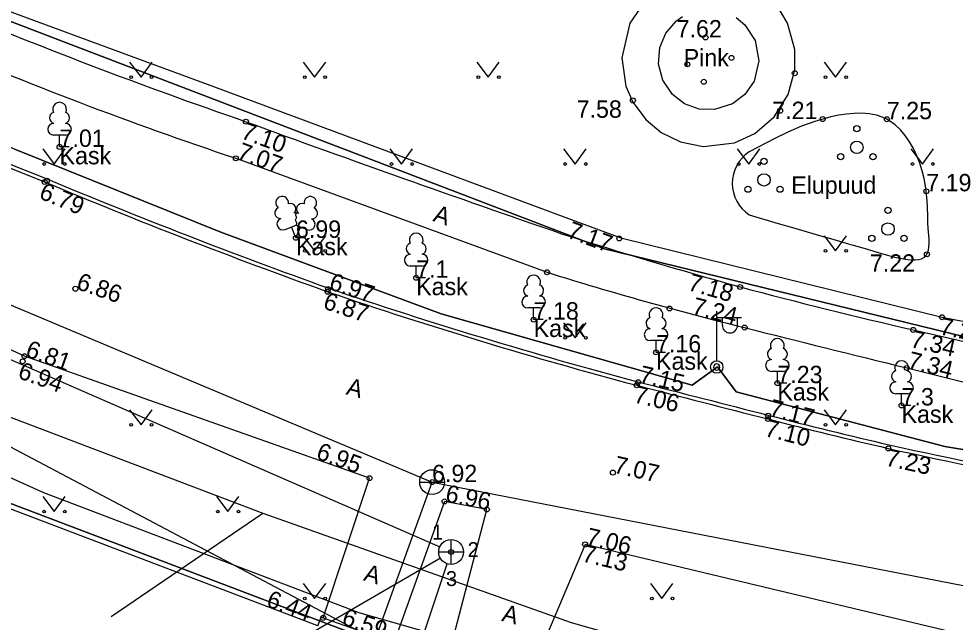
# Model space of a CAD drawing. Extents: x 473307 to 473719, y 6532843 to 6533381.
# Drawn here: x 473584.01 to 473621.77, y 6532915.94 to 6532940.25 of the extents above; entities that cross this region are included whole.
import ezdxf

# ---------------------------------------------------------------- set-up
doc = ezdxf.new("R2010")
doc.units = 0
for name, color, linetype in [('AED', 7, 'Continuous'), ('Default', 7, 'Continuous'), ('HALJASTUS', 7, 'Continuous'), ('KKAEV', 7, 'Continuous'), ('KKAEV_NR', 7, 'Continuous'), ('KORGUS', 7, 'Continuous'), ('KPKAABEL', 7, 'Continuous'), ('KTRASS', 7, 'Continuous'), ('MPKAABEL', 7, 'Continuous'), ('MPOHULIIN', 7, 'Continuous'), ('PIIR', 7, 'Continuous'), ('POST', 7, 'Continuous'), ('PUU', 7, 'Continuous'), ('RAJATIS', 7, 'Continuous'), ('SITRASS', 7, 'Continuous'), ('TEE', 7, 'Continuous'), ('VKAEV', 7, 'Continuous'), ('VTRASS', 7, 'Continuous')]:
    doc.layers.add(name, color=color, linetype=linetype)

# ---------------------------------------------------------------- blocks, each defined once
blk = doc.blocks.new('VEKAEV')
at = {"layer": 'Default'}
blk.add_line((-1, 0), (1, 0), dxfattribs=at)
blk.add_circle((0, 0), 1, dxfattribs=at)
blk = doc.blocks.new('LEHTP1')
at = {"layer": 'Default'}
for p, q in [((0.48, 0.95), (-0.48, 0.95)), ((0, 0), (0, 0.95)), ((0.76, 0), (0, 0))]:
    blk.add_line(p, q, dxfattribs=at)
for centre, radius, start, end in [((0, 3.04), 0.554, 332.5799, 207.4201), ((-0.34, 2.345), 0.465, 109.02174, 253.14154), ((0.34, 2.345), 0.465, 286.85082, 70.98591), ((-0.475, 1.425), 0.475, 90.0016, 269.3953), ((0.475, 1.425), 0.475, 270.6047, 89.9984)]:
    blk.add_arc(centre, radius, start, end, dxfattribs=at)
blk = doc.blocks.new('MEPOST')
at = {"layer": 'Default'}
blk.add_circle((0, 0), 0.5, dxfattribs=at)
for start, end in [(0, 180), (180, 0)]:
    blk.add_arc((0, 0), 0.25, start, end, dxfattribs=at)
blk = doc.blocks.new('VAPOST')
at = {"layer": 'Default'}
for p, q in [((0, 0.5), (0, 4.5)), ((0, 4), (2, 4)), ((0.453, 3.358), (0.453, 4)), ((1.679, 3.358), (1.679, 4))]:
    blk.add_line(p, q, dxfattribs=at)
blk.add_arc((1.066, 3.358), 0.613, 180, 0, dxfattribs=at)
blk = doc.blocks.new('LEHTP2')
at = {"layer": 'Default'}
for p, q in [((-0.88, 0.67), (0.01, 1.02)), ((0, 0), (-0.35, 0.88)), ((0, 0), (0.36, 0.88)), ((0.01, 1.02), (0.89, 0.66)), ((0.76, 0), (0, 0))]:
    blk.add_line(p, q, dxfattribs=at)
blk.add_lwpolyline([(0.01, 2.01), (-0.03, 1.86), (-0.03, 1.82), (-0.01, 1.76), (0.03, 1.69), (0.04, 1.65), (0.01, 1.58), (-0.04, 1.48), (-0.05, 1.43), (-0.04, 1.4), (-0.02, 1.34), (0.05, 1.22), (0.06, 1.18), (0.05, 1.14), (0.02, 1.07), (0.01, 1.02)], dxfattribs=at)
for centre, radius, start, end in [((-1.114, 2.828), 0.512, 111.50269, 232.51731), ((-1.114, 2.828), 0.512, 350.48556, 111.50017), ((1.158, 2.811), 0.512, 67.6168, 188.63142), ((1.158, 2.811), 0.512, 306.59966, 67.61428), ((-1.262, 2.005), 0.448, 111.43041, 274.49868), ((-0.445, 2.327), 0.448, 308.50412, 111.57247), ((0.481, 2.318), 0.45, 67.7016, 230.51262), ((1.293, 1.986), 0.448, 264.6183, 67.68657), ((-1.053, 1.117), 0.475, 111.50143, 291.50036), ((0.008, 1.535), 0.475, 66.76552, 111.50149), ((1.07, 1.101), 0.475, 247.61661, 67.61554)]:
    blk.add_arc(centre, radius, start, end, dxfattribs=at)
blk = doc.blocks.new('PQQSAS')
at = {"layer": 'Default'}
for centre, radius in [((0, 1.5), 0.25), ((0, 0), 0.5), ((-1.3, -0.75), 0.25), ((1.3, -0.75), 0.25)]:
    blk.add_circle(centre, radius, dxfattribs=at)
blk = doc.blocks.new('MURU')
at = {"layer": 'Default'}
for p, q in [((-0.927, 1.213), (0, 0)), ((0, 0), (0.891, 1.213))]:
    blk.add_line(p, q, dxfattribs=at)
for centre in [(-0.802, 0), (0.856, 0)]:
    blk.add_circle(centre, 0.11, dxfattribs=at)
blk = doc.blocks.new('KAKAEV')
at = {"layer": 'Default'}
for p, q in [((0, -1), (0, 1)), ((-1, 0), (1, 0))]:
    blk.add_line(p, q, dxfattribs=at)
blk.add_circle((0, 0), 1, dxfattribs=at)

msp = doc.modelspace()

# ---------------------------------------------------------------- linework, layer by layer
at = {"layer": 'AED'}
for points in [[(473550.051, 6532959.211), (473554.174, 6532956.453), (473573.719, 6532945.513), (473580.254, 6532941.8), (473591.86, 6532937.524), (473605.919, 6532932.298), (473608.286, 6532931.42), (473621.231, 6532928.229), (473637.541, 6532925.082), (473652.528, 6532925.143), (473654.3, 6532926.84), (473651.933, 6532941.676), (473648.983, 6532959.55), (473630.652, 6532956.493)], [(473596.066, 6532915.794), (473579.402, 6532922.119), (473578.304, 6532919.387)]]:
    msp.add_lwpolyline(points, dxfattribs=at)
at = {"layer": 'HALJASTUS'}
msp.add_lwpolyline([(473613.459, 6532932.357), (473614.63, 6532932.01), (473615.203, 6532931.841), (473616.022, 6532931.602), (473616.297, 6532931.522), (473616.824, 6532931.37), (473617.366, 6532931.214), (473617.651, 6532931.132), (473617.949, 6532931.045), (473618.264, 6532930.954), (473618.651, 6532930.84), (473619.317, 6532930.654), (473619.672, 6532930.577), (473619.84, 6532930.552), (473619.999, 6532930.539), (473620.148, 6532930.539), (473620.283, 6532930.554), (473620.402, 6532930.587), (473620.504, 6532930.639), (473620.586, 6532930.712), (473620.622, 6532930.762), (473620.685, 6532930.928), (473620.706, 6532931.065), (473620.713, 6532931.216), (473620.709, 6532931.377), (473620.678, 6532931.822), (473620.665, 6532932.035), (473620.653, 6532932.34), (473620.631, 6532932.921), (473620.597, 6532933.301), (473620.567, 6532933.509), (473620.508, 6532933.815), (473620.431, 6532934.123), (473620.333, 6532934.43), (473620.217, 6532934.731), (473620.081, 6532935.02), (473619.926, 6532935.295), (473619.751, 6532935.549), (473619.557, 6532935.779), (473619.343, 6532935.979), (473619.007, 6532936.203), (473618.855, 6532936.274), (473618.583, 6532936.364), (473618.296, 6532936.419), (473617.998, 6532936.443), (473617.691, 6532936.439), (473617.38, 6532936.412), (473617.066, 6532936.363), (473616.755, 6532936.297), (473616.42, 6532936.21), (473616.148, 6532936.128), (473615.572, 6532935.923), (473615.02, 6532935.688), (473614.487, 6532935.433), (473613.451, 6532934.886)], dxfattribs=at)
msp.add_arc((473614.292, 6532933.624), 1.516, 123.6671, 236.6842, dxfattribs=at)
at = {"layer": 'KKAEV_NR'}
msp.add_lwpolyline([(473601.006, 6532918.524), (473593.029, 6532913.897), (473590.176, 6532913.897)], dxfattribs=at)
at = {"layer": 'KORGUS'}
for centre in [(473611.698, 6532939.497), (473612.743, 6532938.673), (473610.964, 6532938.415), (473615.296, 6532938.057), (473611.626, 6532937.712), (473608.768, 6532936.962), (473614.701, 6532936.546), (473593.167, 6532936.104), (473616.42, 6532936.21), (473619.007, 6532936.203), (473585.655, 6532935.088), (473592.764, 6532934.629), (473585.052, 6532933.677), (473585.146, 6532933.728), (473620.597, 6532933.301), (473595.184, 6532931.426), (473608.22, 6532931.402), (473620.622, 6532930.762), (473605.306, 6532930.039), (473600.032, 6532929.817), (473586.292, 6532929.376), (473596.461, 6532929.256), (473596.475, 6532929.367), (473613.09, 6532929.448), (473610.245, 6532928.58), (473604.767, 6532928.132), (473621.231, 6532928.229), (473613.273, 6532927.812), (473620.072, 6532927.718), (473584.24, 6532926.661), (473609.701, 6532926.814), (473584.167, 6532926.451), (473619.807, 6532926.185), (473608.924, 6532925.487), (473608.984, 6532925.612), (473614.593, 6532925.573), (473619.6, 6532924.675), (473614.214, 6532924.13), (473614.22, 6532924.262), (473619.066, 6532922.945), (473598.15, 6532921.747), (473607.963, 6532921.971), (473600.672, 6532921.587), (473601.176, 6532920.808), (473602.882, 6532920.487), (473606.841, 6532919.08), (473601.438, 6532918.775), (473596.286, 6532916.121)]:
    msp.add_circle(centre, 0.1, dxfattribs=at)
at = {"layer": 'KPKAABEL'}
msp.add_lwpolyline([(473552.428, 6532965.743), (473552.248, 6532955.743), (473551.396, 6532952.25), (473548.538, 6532944.595), (473546.922, 6532939.52), (473555.37, 6532934.798), (473562.977, 6532930.797), (473573.936, 6532926.157), (473585.002, 6532921.176), (473597.713, 6532916.33), (473608.101, 6532913.364), (473620.133, 6532910.115), (473635.44, 6532908.143), (473647.319, 6532907.126), (473658.175, 6532907.682), (473669.898, 6532907.954), (473678.245, 6532908.166), (473679.837, 6532908.723), (473681.3, 6532908.756), (473682.619, 6532907.437), (473683.14, 6532903.797)], dxfattribs=at)
at = {"layer": 'KTRASS'}
for p, q in [((473561.006, 6532936.411), (473600.98, 6532918.975)), ((473599.948, 6532914.317), (473601.28, 6532918.301))]:
    msp.add_line(p, q, dxfattribs=at)
at = {"layer": 'MPKAABEL'}
for points in [[(473647.086, 6532975.076), (473649.618, 6532958.912), (473652.026, 6532944.888), (473654.472, 6532932.695), (473654.676, 6532926.56), (473653.253, 6532921.9), (473652.318, 6532920.677), (473651.722, 6532919.499), (473641.323, 6532920.251), (473631.817, 6532921.274), (473621.345, 6532923.026), (473612.93, 6532925.228), (473612.182, 6532926.232), (473611.163, 6532925.494), (473601.042, 6532928.37), (473592.161, 6532931.655), (473583.871, 6532934.989)], [(473574.304, 6532941.029), (473574.03, 6532940.034), (473574.572, 6532939.314), (473583.871, 6532934.989), (473592.161, 6532931.655), (473601.042, 6532928.37), (473611.163, 6532925.494), (473612.182, 6532926.232)], [(473612.182, 6532926.232), (473612.93, 6532925.228), (473621.345, 6532923.026), (473631.817, 6532921.274), (473641.323, 6532920.251), (473651.722, 6532919.499), (473652.318, 6532920.677)]]:
    msp.add_lwpolyline(points, dxfattribs=at)
at = {"layer": 'MPOHULIIN'}
msp.add_lwpolyline([(473423.194, 6533272.897), (473391.791, 6533270.484), (473361.09, 6533267.919), (473364.229, 6533220.925), (473380.477, 6533175.317), (473396.165, 6533131.758), (473413.567, 6533083.532), (473430.968, 6533052.6), (473459.84, 6533016.944), (473493.252, 6532975.715), (473524.159, 6532957.128), (473561.498, 6532934.712), (473599.705, 6532914.54), (473648.184, 6532910.183)], dxfattribs=at)
at = {"layer": 'PIIR'}
for points in [[(473486.57, 6533007.64), (473478.82, 6533017), (473548.5, 6533028.91), (473572.63, 6533056.43), (473618.6, 6533063.82), (473630.89, 6533065.72), (473654.16, 6532926.37), (473652.82, 6532924.82), (473637.7, 6532924.6), (473625.07, 6532926.73), (473607.63, 6532930.98), (473579.04, 6532941.93), (473554.34, 6532955.84), (473531.51, 6532970.21), (473509.62, 6532987.09)], [(473590.66, 6532884.69), (473567.33, 6532893.22), (473579.89, 6532922.16), (473600.1, 6532914.5)]]:
    msp.add_lwpolyline(points, close=True, dxfattribs=at)
msp.add_lwpolyline([(473455.33, 6533045.76), (473478.82, 6533017), (473486.57, 6533007.64), (473509.62, 6532987.09), (473531.51, 6532970.21), (473554.34, 6532955.84), (473579.04, 6532941.93), (473607.63, 6532930.98), (473625.07, 6532926.73), (473637.7, 6532924.6), (473652.82, 6532924.82), (473654.16, 6532926.37), (473664.64, 6532927.81), (473668.24, 6532906.4), (473641.69, 6532906.33), (473620.6, 6532909.02), (473600.1, 6532914.5), (473579.89, 6532922.16), (473559.95, 6532931.3), (473540.88, 6532942.28), (473521.95, 6532954.78), (473501.05, 6532969.5), (473492.55, 6532977.62), (473473.12, 6532997.79)], dxfattribs=at)
at = {"layer": 'RAJATIS'}
for points in [[(473609.307, 6532941.041), (473608.644, 6532940.077), (473608.32, 6532938.672), (473608.484, 6532937.54), (473608.765, 6532936.893), (473609.299, 6532936.173), (473609.911, 6532935.667), (473610.688, 6532935.288), (473611.597, 6532935.107), (473612.862, 6532935.257), (473613.678, 6532935.631), (473614.466, 6532936.304), (473615.03, 6532937.194), (473615.302, 6532938.192), (473615.302, 6532939.009), (473615.001, 6532940.076), (473614.611, 6532940.724)], [(473612.932, 6532940.3), (473613.281, 6532940.01), (473613.698, 6532939.371), (473613.849, 6532938.553), (473613.653, 6532937.732), (473613.284, 6532937.199), (473612.782, 6532936.817), (473612.056, 6532936.589), (473611.446, 6532936.611), (473610.852, 6532936.822), (473610.365, 6532937.193), (473609.97, 6532937.776), (473609.803, 6532938.419), (473609.854, 6532939.093), (473610.093, 6532939.663), (473610.526, 6532940.163), (473610.774, 6532940.339)]]:
    msp.add_lwpolyline(points, dxfattribs=at)
at = {"layer": 'SITRASS'}
for points in [[(473550.519, 6532939.382), (473577.394, 6532926.586), (473593.851, 6532920.336), (473606.277, 6532915.93), (473618.378, 6532912.493)], [(473587.73, 6532916.17), (473593.851, 6532920.336)]]:
    msp.add_lwpolyline(points, dxfattribs=at)
at = {"layer": 'TEE'}
for points in [[(473596.285, 6532916.119), (473598.15, 6532921.747), (473584.24, 6532926.661), (473566.831, 6532934.624), (473564.204, 6532928.869)], [(473592.764, 6532934.629), (473605.306, 6532930.039)], [(473620.072, 6532927.718), (473626.78, 6532926.195)], [(473636.219, 6532907.347), (473636.647, 6532912.933), (473625.183, 6532914.695), (473606.841, 6532919.08), (473604.405, 6532913.308), (473601.232, 6532914.16), (473602.882, 6532920.487), (473601.176, 6532920.808), (473599.124, 6532915.109)], [(473596.066, 6532915.794), (473596.201, 6532916.151), (473599.209, 6532915.082), (473599.048, 6532914.586)]]:
    msp.add_lwpolyline(points, dxfattribs=at)
for centre, radius, start, end in [((473662.369, 6533136.344), 211.861, 247.32056, 250.93503), ((473643.903, 6533087.766), 161.45, 246.77511, 251.53347), ((473641.39, 6533075.267), 152.387, 245.24469, 248.30262), ((473641.39, 6533075.267), 152.237, 245.24536, 248.30311), ((473858.331, 6533663.952), 774.645, 249.982673, 250.981556), ((473675.347, 6533149.763), 234.193, 247.32169, 250.3155), ((473675.347, 6533149.763), 234.043, 247.32138, 250.31523), ((473673.614, 6533145.675), 224.538, 252.44702, 254.36265), ((473645.8, 6533059.539), 135.684, 252.63595, 256.12971), ((473656.652, 6533105.807), 186.379, 251.17458, 255.17421), ((473672.666, 6533154.932), 233.222, 255.19993, 256.96714), ((473656.652, 6533105.807), 186.529, 251.17423, 255.17436), ((473866.174, 6533929.523), 1033.142, 255.830701, 256.204127), ((473666.197, 6533109.975), 189.554, 255.83389, 257.71252), ((474385.5, 6535941.573), 3114.307, 255.561206, 255.661678), ((474385.5, 6535941.573), 3114.457, 255.561197, 255.661675), ((473663.654, 6533116.039), 198.175, 255.55334, 256.9974), ((473663.654, 6533116.039), 198.025, 255.5533, 256.99722), ((473665.577, 6533132.48), 214.635, 257.48495, 259.58307), ((473665.577, 6533132.48), 214.485, 257.48512, 259.58328)]:
    msp.add_arc(centre, radius, start, end, dxfattribs=at)
at = {"layer": 'VTRASS'}
for points in [[(473503.731, 6532976.927), (473535.265, 6532954.21), (473555.891, 6532941.175), (473565.122, 6532936.508), (473600.672, 6532921.587), (473636.512, 6532914.617), (473674.923, 6532915.363), (473675.557, 6532915.427)], [(473598.193, 6532914.706), (473600.672, 6532921.587)]]:
    msp.add_lwpolyline(points, dxfattribs=at)

# ---------------------------------------------------------------- block references
at = {"layer": 'HALJASTUS', "xscale": 0.5, "yscale": 0.5}
for name, p in [('MURU', (473588.938, 6532937.899)), ('MURU', (473595.938, 6532937.899)), ('MURU', (473602.938, 6532937.899)), ('MURU', (473616.938, 6532937.899)), ('PQQSAS', (473617.796, 6532935.071)), ('MURU', (473585.438, 6532934.399)), ('MURU', (473599.438, 6532934.399)), ('MURU', (473606.438, 6532934.399)), ('MURU', (473613.438, 6532934.399)), ('MURU', (473620.438, 6532934.399)), ('PQQSAS', (473614.054, 6532933.76)), ('PQQSAS', (473619.052, 6532931.78)), ('MURU', (473595.938, 6532930.899)), ('MURU', (473616.938, 6532930.899)), ('MURU', (473606.438, 6532927.399)), ('MURU', (473588.938, 6532923.899)), ('MURU', (473616.938, 6532923.899)), ('MURU', (473585.438, 6532920.399)), ('MURU', (473592.438, 6532920.399)), ('MURU', (473595.938, 6532916.899)), ('MURU', (473609.938, 6532916.899))]:
    msp.add_blockref(name, p, dxfattribs=at)
at = {"layer": 'KKAEV', "xscale": 0.5, "yscale": 0.5}
msp.add_blockref('KAKAEV', (473601.438, 6532918.775), dxfattribs=at)
at = {"layer": 'POST', "xscale": 0.5, "yscale": 0.5}
for name in ['VAPOST', 'MEPOST']:
    msp.add_blockref(name, (473612.148, 6532926.223), dxfattribs=at)
at = {"layer": 'PUU', "xscale": 0.5, "yscale": 0.5}
for name, p in [('LEHTP1', (473585.655, 6532935.088)), ('LEHTP2', (473595.184, 6532931.426)), ('LEHTP1', (473600.032, 6532929.817)), ('LEHTP1', (473604.767, 6532928.132)), ('LEHTP1', (473609.701, 6532926.814)), ('LEHTP1', (473614.593, 6532925.573)), ('LEHTP1', (473619.6, 6532924.675))]:
    msp.add_blockref(name, p, dxfattribs=at)
at = {"layer": 'VKAEV', "xscale": 0.5, "yscale": 0.5}
msp.add_blockref('VEKAEV', (473600.672, 6532921.587), dxfattribs=at)

# ---------------------------------------------------------------- texts
at = {"layer": 'HALJASTUS'}
msp.add_text('Elupuud', height=0.7, dxfattribs=at).set_placement((473615.15, 6532933.201))
at = {"layer": 'KKAEV_NR'}
for s, p in [('1', (473600.669, 6532919.276)), ('2', (473602.107, 6532918.572)), ('3', (473601.232, 6532917.403))]:
    msp.add_text(s, height=0.6, dxfattribs=at).set_placement(p)
at = {"layer": 'KORGUS'}
for s, p in [('7.62', (473610.531, 6532939.497)), ('7.58', (473606.501, 6532936.262)), ('7.21', (473614.387, 6532936.21)), ('7.25', (473619.007, 6532936.203)), ('7.19', (473620.597, 6532933.301)), ('7.22', (473618.322, 6532930.062))]:
    msp.add_text(s, height=0.7, dxfattribs=at).set_placement(p)
for s, rotation, p in [('7.01', 0.04, (473585.655, 6532935.088)), ('7.10', 340.0463, (473592.928, 6532935.446)), ('7.07', 339.8989, (473592.764, 6532934.629)), ('6.79', 337.5823, (473584.785, 6532933.03)), ('6.99', 0.04, (473595.184, 6532931.426)), ('7.17', 339.6313, (473606.07, 6532931.453)), ('7.1', 0.04, (473600.032, 6532929.817)), ('6.86', 341.1727, (473586.292, 6532929.376)), ('6.97', 341.5003, (473596.475, 6532929.367)), ('7.18', 344.0276, (473610.943, 6532929.335)), ('6.87', 341.5003, (473596.239, 6532928.592)), ('7.24', 345.6256, (473611.11, 6532928.366)), ('7.18', 0.04, (473604.767, 6532928.132)), ('7.28', 349.079, (473621.098, 6532927.542)), ('7.16', 0.04, (473609.701, 6532926.814)), ('7.34', 347.2083, (473619.917, 6532927.035)), ('6.81', 340.4181, (473584.24, 6532926.661)), ('7.34', 346.1408, (473619.807, 6532926.185)), ('6.94', 340.4181, (473583.932, 6532925.791)), ('7.15', 347.0866, (473608.984, 6532925.612)), ('7.23', 0.04, (473614.593, 6532925.573)), ('7.06', 347.0866, (473608.767, 6532924.805)), ('7.3', 0.04, (473619.6, 6532924.675)), ('7.17', 345.8965, (473614.22, 6532924.262)), ('7.10', 345.8965, (473614.043, 6532923.451)), ('6.95', 340, (473595.957, 6532922.545)), ('7.23', 347.7902, (473618.918, 6532922.261)), ('7.07', 347.3309, (473607.963, 6532921.971)), ('6.92', 0.04, (473600.672, 6532921.587)), ('6.96', 348.6476, (473601.176, 6532920.808)), ('7.06', 346.8366, (473606.841, 6532919.08)), ('7.13', 346.8366, (473606.682, 6532918.398)), ('6.44', 339.2152, (473593.947, 6532916.598)), ('6.59', 340.2797, (473596.99, 6532915.874))]:
    msp.add_text(s, height=0.7, rotation=rotation, dxfattribs=at).set_placement(p)
at = {"layer": 'PUU'}
for p in [(473585.655, 6532934.388), (473595.184, 6532930.726), (473600.032, 6532929.117), (473604.767, 6532927.432), (473609.701, 6532926.114), (473614.593, 6532924.873), (473619.6, 6532923.975)]:
    msp.add_text('Kask', height=0.7, dxfattribs=at).set_placement(p)
at = {"layer": 'RAJATIS'}
msp.add_text('Pink', height=0.7, dxfattribs=at).set_placement((473610.817, 6532938.333))
at = {"layer": 'TEE'}
for rotation, p in [(341.7915, (473600.672, 6532932.109)), (344.8634, (473597.173, 6532925.129)), (343.377, (473597.875, 6532917.637)), (345.3504, (473603.447, 6532916.004))]:
    msp.add_text('A', height=0.7, rotation=rotation, dxfattribs=at).set_placement(p)

doc.saveas('drawing.dxf')
